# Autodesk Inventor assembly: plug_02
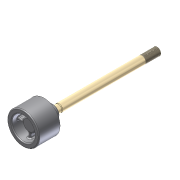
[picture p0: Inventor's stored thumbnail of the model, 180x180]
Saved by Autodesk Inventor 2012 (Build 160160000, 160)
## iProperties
Created: 2002-07
Part Number: plug_02
Document SubType Name: Assembly
Designer: Lieven Grauls
Stock Number: plug_02
Project: Valve Techcamp 2008
Mass: 72.6694 g
Surface Area: 260.344 cm^2
Volume: 72.6694 cm^3
Density: 1 g/cm^3
Company: Autodesk
Control State: 0
Master: False
Checked Out: False
Shininess: 64.0
Length Units: 11269
Angle Units: 11279
Time Units: 11290
Mass Units: 11283
Length Display Precision: 3
Angle Display Precision: 2
Density: 0.0
Volumn: 0.0
Area: 0.0
PropertySet Name: Model Information
Author: Lieven Grauls
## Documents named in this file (3)
- C:\CMU\Week 14\Problem set\Valve\Assemblies\plug_02.iam
- C:\CMU\Week 14\Problem set\Valve\Parts\plug_mch_02.ipt
- C:\CMU\Week 14\Problem set\Valve\Parts\stem_02.ipt
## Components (2 placed, 2 different names)
1. plug_mch_02:1 — Mate:1, Tangent:1, Mate:3
2. stem_02:1 — Mate:1, Mate:2, Mate:3
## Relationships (4: Mate 3, Tangent 1)
- Mate:1: plug_mch_02:1 ↔ stem_02:1
- Mate:2: stem_02:1
- Tangent:1: plug_mch_02:1
- Mate:3: plug_mch_02:1 ↔ stem_02:1
